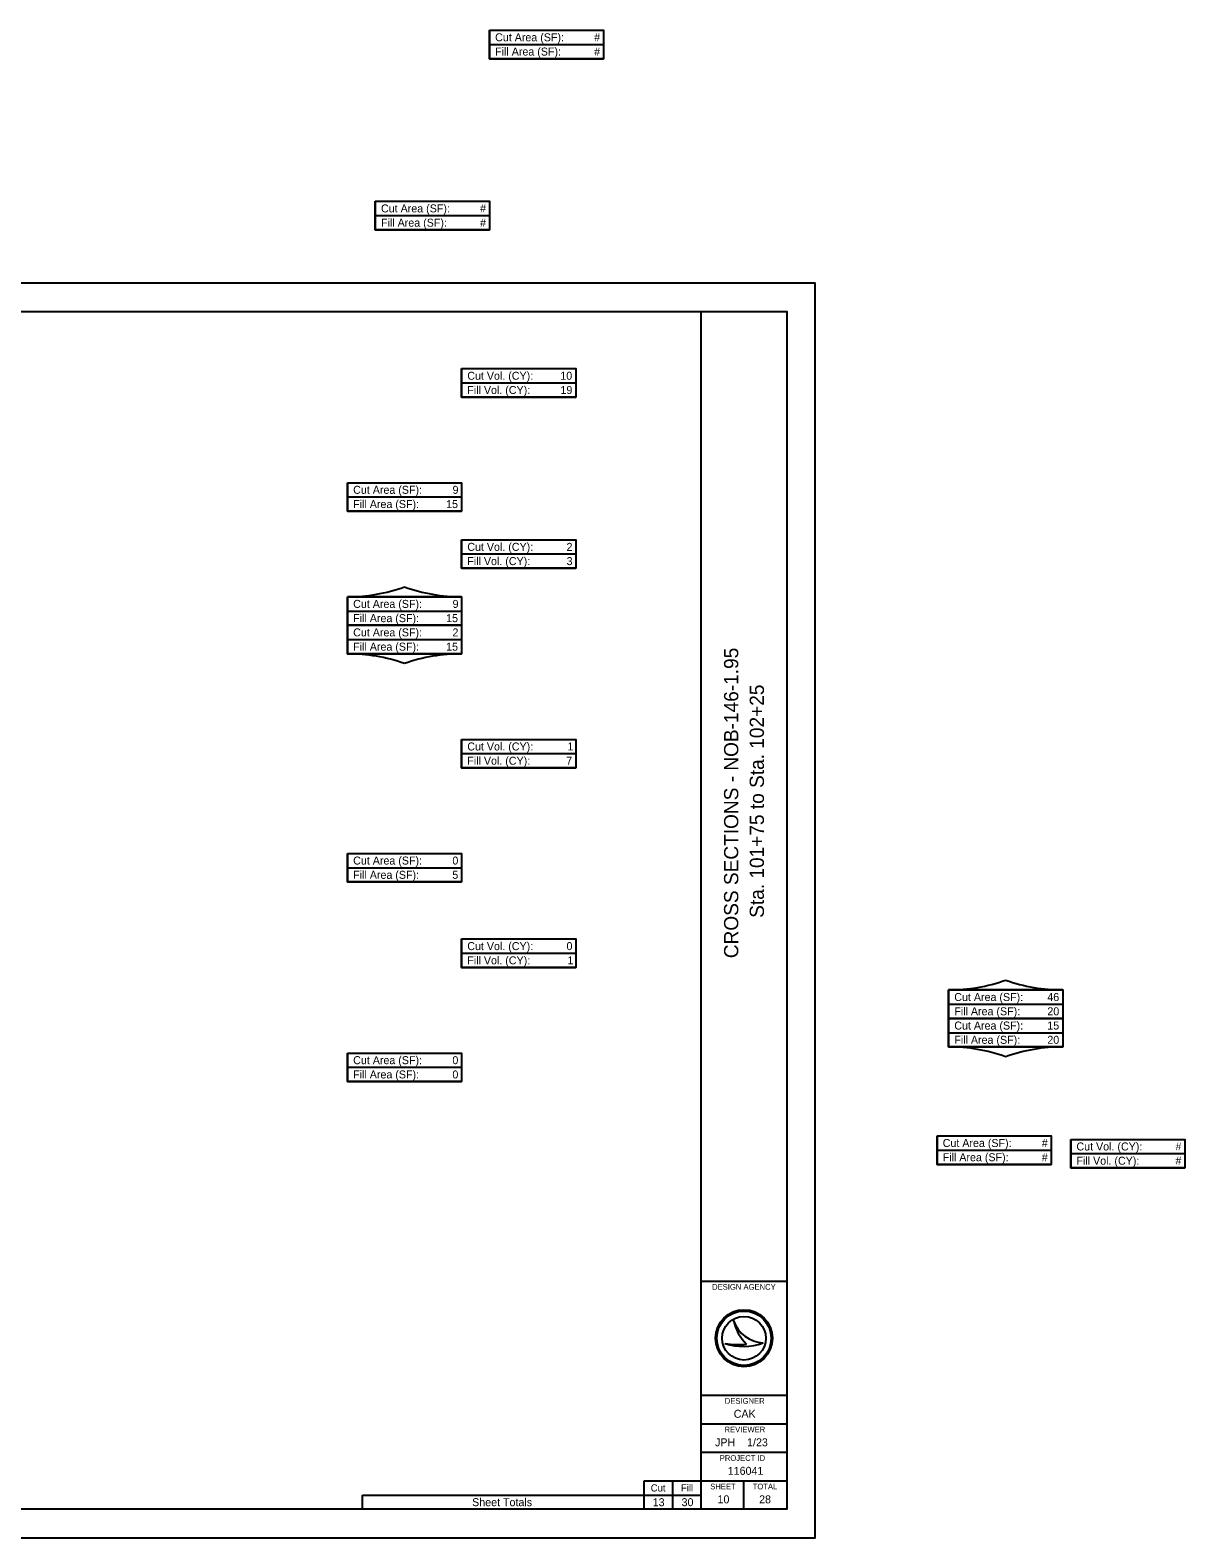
# Model space of a CAD drawing. Extents: x -46 to 154, y -27 to 78.
# Drawn here: x 20.24 to 40.48, y 0 to 26.43 of the extents above; entities that cross this region are included whole.
import ezdxf

# ---------------------------------------------------------------- set-up
doc = ezdxf.new("R2010")
doc.units = 0
for name, color, linetype in [('Default', 7, 'Continuous'), ('DT_X_Contour_Major', 7, 'Continuous'), ('DT_X_Contour_Minor', 7, 'Continuous'), ('DT_X_Spot_Elev', 7, 'Continuous'), ('DT_X_Void', 7, 'Continuous'), ('SH_Text', 7, 'Continuous')]:
    doc.layers.add(name, color=color, linetype=linetype)

msp = doc.modelspace()

# ---------------------------------------------------------------- linework, layer by layer
at = {"layer": 'Default'}
for p, q in [((31, 0.5), (31, 1)), ((31.5, 0.5), (31.5, 1)), ((26.064, 0.5), (26.064, 0.75))]:
    msp.add_line(p, q, dxfattribs=at)
at = {"layer": 'DT_X_Contour_Major'}
msp.add_lwpolyline([(0, 0), (34, 0), (34, 22), (0, 22)], close=True, dxfattribs=at)
at = {"layer": 'DT_X_Contour_Minor'}
for p, q in [((28.288, 26.434), (30.288, 26.434)), ((28.288, 26.434), (28.288, 25.934)), ((30.288, 26.434), (30.288, 25.934)), ((28.288, 26.184), (30.288, 26.184)), ((28.288, 25.934), (30.288, 25.934)), ((26.288, 23.434), (28.288, 23.434)), ((26.288, 23.434), (26.288, 22.934)), ((28.288, 23.434), (28.288, 22.934)), ((26.288, 23.184), (28.288, 23.184)), ((26.288, 22.934), (28.288, 22.934)), ((27.8, 20.5), (29.8, 20.5)), ((27.8, 20.5), (27.8, 20)), ((29.8, 20.5), (29.8, 20)), ((27.8, 20.25), (29.8, 20.25)), ((27.8, 20), (29.8, 20)), ((25.8, 18.5), (27.8, 18.5)), ((25.8, 18.5), (25.8, 18)), ((25.8, 18.25), (27.8, 18.25)), ((27.8, 18.5), (27.8, 18)), ((25.8, 18), (27.8, 18)), ((27.8, 17.5), (29.8, 17.5)), ((27.8, 17.5), (27.8, 17)), ((29.8, 17.5), (29.8, 17)), ((27.8, 17.25), (29.8, 17.25)), ((27.8, 17), (29.8, 17)), ((25.8, 16.5), (27.8, 16.5)), ((25.8, 16.5), (25.8, 16)), ((27.8, 16.5), (25.8, 16.5)), ((27.8, 16.5), (27.8, 16)), ((25.8, 16.25), (27.8, 16.25)), ((25.8, 16), (27.8, 16)), ((25.8, 16), (27.8, 16)), ((25.8, 16), (25.8, 15.5)), ((27.8, 16), (27.8, 15.5)), ((25.8, 15.75), (27.8, 15.75)), ((25.8, 15.5), (27.8, 15.5)), ((27.8, 15.5), (25.8, 15.5)), ((27.8, 14), (29.8, 14)), ((27.8, 14), (27.8, 13.5)), ((27.8, 13.75), (29.8, 13.75)), ((29.8, 14), (29.8, 13.5)), ((27.8, 13.5), (29.8, 13.5)), ((25.8, 12), (27.8, 12)), ((25.8, 12), (25.8, 11.5)), ((27.8, 12), (27.8, 11.5)), ((25.8, 11.75), (27.8, 11.75)), ((25.8, 11.5), (27.8, 11.5)), ((27.8, 10.5), (29.8, 10.5)), ((27.8, 10.5), (27.8, 10)), ((29.8, 10.5), (29.8, 10)), ((27.8, 10.25), (29.8, 10.25)), ((27.8, 10), (29.8, 10)), ((36.336, 9.607), (38.336, 9.607)), ((36.336, 9.607), (36.336, 9.107)), ((38.336, 9.607), (36.336, 9.607)), ((38.336, 9.607), (38.336, 9.107)), ((36.336, 9.357), (38.336, 9.357)), ((36.336, 9.107), (38.336, 9.107)), ((36.336, 9.107), (38.336, 9.107)), ((36.336, 9.107), (36.336, 8.607)), ((38.336, 9.107), (38.336, 8.607)), ((36.336, 8.857), (38.336, 8.857)), ((25.8, 8.5), (27.8, 8.5)), ((25.8, 8.5), (25.8, 8)), ((27.8, 8.5), (27.8, 8)), ((36.336, 8.607), (38.336, 8.607)), ((38.336, 8.607), (36.336, 8.607)), ((25.8, 8.25), (27.8, 8.25)), ((25.8, 8), (27.8, 8)), ((36.133, 7.048), (38.133, 7.048)), ((36.133, 7.048), (36.133, 6.548)), ((38.133, 7.048), (38.133, 6.548)), ((38.477, 6.987), (40.477, 6.987)), ((38.477, 6.987), (38.477, 6.487)), ((40.477, 6.987), (40.477, 6.487)), ((36.133, 6.798), (38.133, 6.798)), ((38.477, 6.737), (40.477, 6.737)), ((36.133, 6.548), (38.133, 6.548)), ((38.477, 6.487), (40.477, 6.487)), ((32.567, 3.81), (32.567, 3.81)), ((32.75, 3.5), (32.75, 3.5)), ((32.417, 3.41), (32.417, 3.41)), ((33.087, 3.419), (33.087, 3.419)), ((31, 1), (32, 1)), ((32.75, 0.5), (32.75, 1)), ((26.064, 0.75), (32, 0.75)), ((32.375, 0.675), (32.375, 0.675))]:
    msp.add_line(p, q, dxfattribs=at)
for radius in [0.5, 0.477, 0.477, 0.382]:
    msp.add_circle((32.75, 3.5), radius, dxfattribs=at)
for centre, radius, start, end in [((25.8, 19.5), 3, 270, 289.4712), ((27.8, 19.5), 3, 250.5288, 270), ((25.8, 12.5), 3, 70.5288, 90), ((27.8, 12.5), 3, 90, 109.4712), ((36.336, 12.607), 3, 270, 289.4712), ((38.336, 12.607), 3, 250.5288, 270), ((36.336, 5.607), 3, 70.5288, 90), ((38.336, 5.607), 3, 90, 109.4712), ((33.116, 3.998), 0.58, 198.9257, 198.9319), ((33.347, 3.97), 0.796, 191.6379, 191.6421), ((33.116, 3.998), 0.58, 198.9319, 267.1657), ((33.347, 3.97), 0.796, 191.6421, 226.0947), ((32.739, 4.37), 1.013, 251.4576, 290.0832), ((32.648, 4.654), 1.266, 259.4964, 259.4995), ((32.739, 4.37), 1.013, 251.4527, 251.4576), ((32.648, 4.654), 1.266, 259.4995, 276.6672)]:
    msp.add_arc(centre, radius, start, end, dxfattribs=at)
at = {"layer": 'DT_X_Spot_Elev'}
for p, q in [((32, 0.5), (32, 21.5)), ((32, 4.5), (33.5, 4.5)), ((32, 2.5), (33.5, 2.5)), ((32, 2), (33.5, 2)), ((32, 1.5), (33.5, 1.5)), ((32, 1), (33.5, 1))]:
    msp.add_line(p, q, dxfattribs=at)
msp.add_lwpolyline([(1.5, 21.5), (33.5, 21.5), (33.5, 0.5), (1.5, 0.5)], close=True, dxfattribs=at)
at = {"layer": 'SH_Text'}
for points in [[(28.288, 26.434), (30.288, 26.434), (30.288, 25.934), (28.288, 25.934)], [(26.288, 23.434), (28.288, 23.434), (28.288, 22.934), (26.288, 22.934)], [(27.8, 20.5), (29.8, 20.5), (29.8, 20), (27.8, 20)], [(25.8, 18.5), (27.8, 18.5), (27.8, 18), (25.8, 18)], [(27.8, 17.5), (29.8, 17.5), (29.8, 17), (27.8, 17)], [(25.8, 16.5), (27.8, 16.5), (27.8, 16), (25.8, 16)], [(25.8, 16), (27.8, 16), (27.8, 15.5), (25.8, 15.5)], [(27.8, 14), (29.8, 14), (29.8, 13.5), (27.8, 13.5)], [(25.8, 12), (27.8, 12), (27.8, 11.5), (25.8, 11.5)], [(27.8, 10.5), (29.8, 10.5), (29.8, 10), (27.8, 10)], [(36.336, 9.607), (38.336, 9.607), (38.336, 9.107), (36.336, 9.107)], [(36.336, 9.107), (38.336, 9.107), (38.336, 8.607), (36.336, 8.607)], [(25.8, 8.5), (27.8, 8.5), (27.8, 8), (25.8, 8)], [(36.133, 7.048), (38.133, 7.048), (38.133, 6.548), (36.133, 6.548)], [(38.477, 6.987), (40.477, 6.987), (40.477, 6.487), (38.477, 6.487)]]:
    msp.add_lwpolyline(points, close=True, dxfattribs=at)

# ---------------------------------------------------------------- texts
at = {"layer": 'Default'}
for s, height, p in [('Cut', 0.125, (31.115, 0.813)), ('Fill', 0.125, (31.645, 0.813)), ('Sheet Totals', 0.14, (27.985, 0.555)), ('13', 0.14, (31.15, 0.555)), ('30', 0.14, (31.656, 0.555))]:
    msp.add_text(s, height=height, dxfattribs=at).set_placement(p)
at = {"layer": 'DT_X_Contour_Minor'}
for s, p in [('CROSS SECTIONS - NOB-146-1.95', (32.65, 10.163)), ('Sta. 101+75 to Sta. 102+25', (33.1, 10.871))]:
    msp.add_text(s, height=0.25, rotation=90, dxfattribs=at).set_placement(p)
for s, height, p in [('DESIGN AGENCY', 0.1, (32.191, 4.35)), ('DESIGNER', 0.1, (32.414, 2.35)), ('CAK', 0.14, (32.57, 2.105)), ('REVIEWER', 0.1, (32.409, 1.85)), ('JPH    1/23', 0.14, (32.242, 1.605)), ('PROJECT ID', 0.1, (32.325, 1.35)), ('116041', 0.14, (32.465, 1.105)), ('SHEET', 0.1, (32.158, 0.85)), ('TOTAL', 0.1, (32.903, 0.85)), ('10', 0.14, (32.286, 0.605)), ('28', 0.14, (33.015, 0.605))]:
    msp.add_text(s, height=height, dxfattribs=at).set_placement(p)
at = {"layer": 'DT_X_Void'}
for s, p in [('Cut Area (SF):', (28.388, 26.239)), ('#', (30.124, 26.239)), ('Fill Area (SF):', (28.388, 25.989)), ('#', (30.124, 25.989)), ('Cut Area (SF):', (26.388, 23.239)), ('#', (28.124, 23.239)), ('Fill Area (SF):', (26.388, 22.989)), ('#', (28.124, 22.989)), ('Cut Vol. (CY):', (27.9, 20.305)), ('10', (29.531, 20.305)), ('Fill Vol. (CY):', (27.9, 20.055)), ('19', (29.533, 20.055)), ('Cut Area (SF):', (25.9, 18.305)), ('9', (27.642, 18.305)), ('Fill Area (SF):', (25.9, 18.055)), ('15', (27.529, 18.055)), ('Cut Vol. (CY):', (27.9, 17.305)), ('2', (29.64, 17.305)), ('Fill Vol. (CY):', (27.9, 17.055)), ('3', (29.641, 17.055)), ('Cut Area (SF):', (25.9, 16.305)), ('9', (27.642, 16.305)), ('Fill Area (SF):', (25.9, 16.055)), ('15', (27.529, 16.055)), ('Cut Area (SF):', (25.9, 15.805)), ('2', (27.64, 15.805)), ('Fill Area (SF):', (25.9, 15.555)), ('15', (27.529, 15.555)), ('Cut Vol. (CY):', (27.9, 13.805)), ('1', (29.656, 13.805)), ('Fill Vol. (CY):', (27.9, 13.555)), ('7', (29.634, 13.555)), ('Cut Area (SF):', (25.9, 11.805)), ('0', (27.639, 11.805)), ('Fill Area (SF):', (25.9, 11.555)), ('5', (27.638, 11.555)), ('Cut Vol. (CY):', (27.9, 10.305)), ('0', (29.639, 10.305)), ('Fill Vol. (CY):', (27.9, 10.055)), ('1', (29.656, 10.055)), ('Cut Area (SF):', (36.436, 9.412)), ('46', (38.066, 9.412)), ('Fill Area (SF):', (36.436, 9.162)), ('20', (38.067, 9.162)), ('Cut Area (SF):', (36.436, 8.912)), ('15', (38.066, 8.912)), ('Fill Area (SF):', (36.436, 8.662)), ('20', (38.067, 8.662)), ('Cut Area (SF):', (25.9, 8.305)), ('Fill Area (SF):', (25.9, 8.055)), ('0', (27.639, 8.305)), ('0', (27.639, 8.055)), ('Cut Area (SF):', (36.233, 6.853)), ('#', (37.97, 6.853)), ('Cut Vol. (CY):', (38.577, 6.792)), ('#', (40.313, 6.792)), ('Fill Area (SF):', (36.233, 6.603)), ('#', (37.97, 6.603)), ('Fill Vol. (CY):', (38.577, 6.542)), ('#', (40.313, 6.542))]:
    msp.add_text(s, height=0.14, dxfattribs=at).set_placement(p)

doc.saveas('drawing.dxf')
